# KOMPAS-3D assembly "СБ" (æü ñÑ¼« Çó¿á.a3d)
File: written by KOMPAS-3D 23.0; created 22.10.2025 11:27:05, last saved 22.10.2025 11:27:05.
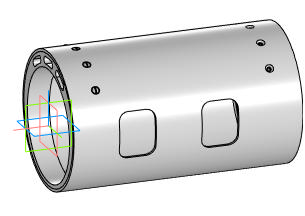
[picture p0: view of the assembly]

Document properties: Автор: ARM_513_VVK; Полное имя файла: F:\Демо\Демо вариант авиация\СБ демо Авиа.a3d

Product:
- Component [detail]: Винт A.М4x12 ГОСТ 17474  | qty 5  | Автор: ARM_513_VVK; source file: Винт A.М4x12 ГОСТ 17474.m3d
- Component [detail]: 3D фрагмент_3  | qty 2  | Автор: ARM_513_VVK; source file: 3D фрагмент_3.m3d
- Component [detail]: 3D фрагмент_2  | qty 1  | Автор: ARM_513_VVK; source file: 3D фрагмент_2.m3d
- Part/product: СБ

Referenced files in F:\Демо\Демо вариант авиация\: Винт A.М4x12 ГОСТ 17474.m3d, 3D фрагмент_3.m3d, 3D фрагмент_2.m3d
